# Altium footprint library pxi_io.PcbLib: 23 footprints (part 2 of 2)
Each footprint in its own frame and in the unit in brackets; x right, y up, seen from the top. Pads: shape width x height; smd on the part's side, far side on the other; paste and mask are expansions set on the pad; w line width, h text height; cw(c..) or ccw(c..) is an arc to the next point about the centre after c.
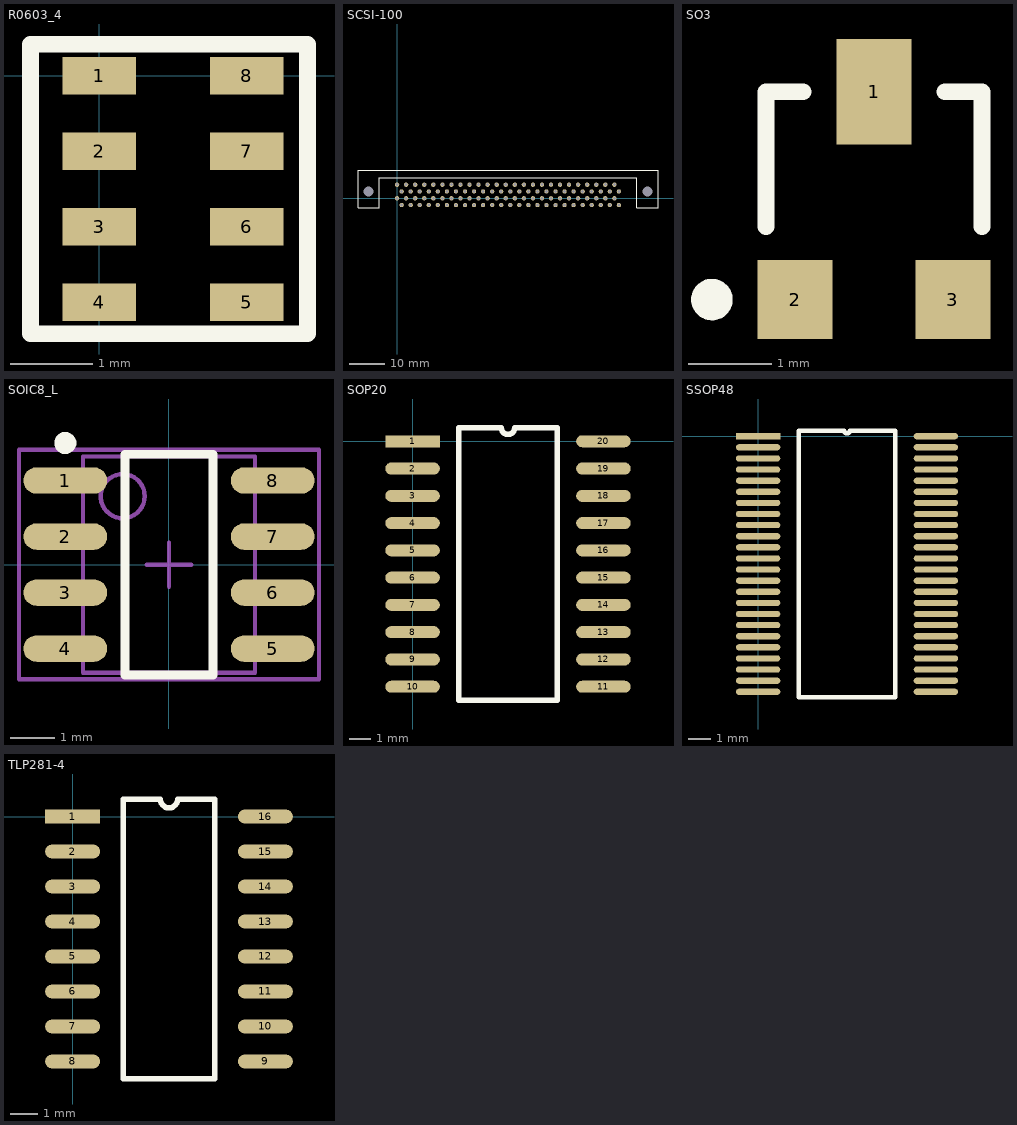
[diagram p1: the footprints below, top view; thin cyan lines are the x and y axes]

## R0603_4 [mil] "for ResPackX4____OK!"
pads (8):
  rect 35x18 smd: 1(0,0) 2(0,-36) 3(0,-72) 4(0,-108) 5(70.16,-108) 6(70.16,-72) 7(70.16,-36) 8(70.16,0)
Top Overlay:
  lines w8: -32.84,15 -32.84,-123 99.16,-123 99.16,15 -31.84,15

## SCSI-100 [mm]
pads (102):
  round 1.2 hole 0.85: 1(0,0) 2(1.27,-1.905) 3(2.54,0) 4(3.81,-1.905) 5(5.08,0) 6(6.35,-1.905) 7(7.62,0) 8(8.89,-1.905) 9(10.16,0) 10(11.43,-1.905) 11(12.7,0) 12(13.97,-1.905) 13(15.24,0) 14(16.51,-1.905) 15(17.78,0) 16(19.05,-1.905) 17(20.32,0) 18(21.59,-1.905) 19(22.86,0) 20(24.13,-1.905) 21(25.4,0) 22(26.67,-1.905) 23(27.94,0) 24(29.21,-1.905) 25(30.48,0) 26(31.75,-1.905) 27(33.02,0) 28(34.29,-1.905) 29(35.56,0) 30(36.83,-1.905) 31(38.1,0) 32(39.37,-1.905) 33(40.64,0) 34(41.91,-1.905) 35(43.18,0) 36(44.45,-1.905) 37(45.72,0) 38(46.99,-1.905) 39(48.26,0) 40(49.53,-1.905) 41(50.8,0) 42(52.07,-1.905) 43(53.34,0) 44(54.61,-1.905) 45(55.88,0) 46(57.15,-1.905) 47(58.42,0) 48(59.69,-1.905) 49(60.96,0) 50(62.23,-1.905) 51(0,3.81) 52(1.27,1.905) 53(2.54,3.81) 54(3.81,1.905) 55(5.08,3.81) 56(6.35,1.905) 57(7.62,3.81) 58(8.89,1.905) 59(10.16,3.81) 60(11.43,1.905) 61(12.7,3.81) 62(13.97,1.905) 63(15.24,3.81) 64(16.51,1.905) 65(17.78,3.81) 66(19.05,1.905) 67(20.32,3.81) 68(21.59,1.905) 69(22.86,3.81) 70(24.13,1.905) 71(25.4,3.81) 72(26.67,1.905) 73(27.94,3.81) 74(29.21,1.905) 75(30.48,3.81) 76(31.75,1.905) 77(33.02,3.81) 78(34.29,1.905) 79(35.56,3.81) 80(36.83,1.905) 81(38.1,3.81) 82(39.37,1.905) 83(40.64,3.81) 84(41.91,1.905) 85(43.18,3.81) 86(44.45,1.905) 87(45.72,3.81) 88(46.99,1.905) 89(48.26,3.81) 90(49.53,1.905) 91(50.8,3.81) 92(52.07,1.905) 93(53.34,3.81) 94(54.61,1.905) 95(55.88,3.81) 96(57.15,1.905) 97(58.42,3.81) 98(59.69,1.905) 99(60.96,3.81) 100(62.23,1.905)
  round 2.5 hole 2.77: 101(-8.01,1.905) 102(70.24,1.905)
Top Overlay:
  lines w0.254: -10.975,-2.667 -10.975,7.858 73.205,7.874 73.205,-2.667 67.265,-2.667 67.265,5.7 -5.035,5.715 -5.035,-2.667 -10.975,-2.667

## SO3 [mm]
pads (3):
  rect 0.9x1.27 smd: 1(2.972,-3.601)
  rect 0.9x0.95 smd: 2(2.022,-6.101) 3(3.922,-6.101)
Top Overlay:
  circle w0.25: c1.022,-6.101 r0.125
  lines w0.2: 1.672,-5.226 1.672,-3.601 2.122,-3.601 ; 3.822,-3.601 4.272,-3.601 4.272,-5.226

## SOIC8_L [mm] "SOIC, 8-Leads, Body 4.9x3.9mm, Pitch 1.27mm, IPC High Density"
height 1.75
pads (8):
  oval 1.9x0.6 smd: 1(-2.35,1.905) 2(-2.35,0.635) 3(-2.35,-0.635) 4(-2.35,-1.905) 5(2.35,-1.905) 6(2.35,-0.635) 7(2.35,0.635) 8(2.35,1.905)
Top Overlay:
  circle w0.25: c-2.35,2.755 r0.125
  lines w0.2: -1,-2.5 1,-2.5 1,2.5 -1,2.5 -1,-2.5
Mechanical 13:
  circle w0.1: c-1.05,1.55 r0.5
  lines w0.1: -1.95,-2.45 1.95,-2.45 1.95,2.45 -1.95,2.45 -1.95,-2.45
Mechanical 15:
  lines w0.1: -0.5,0 0.5,0 ; 0,-0.5 0,0.5 ; -3.4,-2.6 3.4,-2.6 3.4,2.6 -3.4,2.6 -3.4,-2.6
3D body: height 1.75, standoff 0, extent -1.95,-2.45 1.95,2.45

## SOP20 [mil]
pads (20):
  rect 100x22 smd: 1(0,0)
  oval 100x22 smd: 2(0,-50) 3(0,-100) 4(0,-150) 5(0,-200) 6(0,-250) 7(0,-300) 8(0,-350) 9(0,-400) 10(0,-450) 11(350,-450) 12(350,-400) 13(350,-350) 14(350,-300) 15(350,-250) 16(350,-200) 17(350,-150) 18(350,-100) 19(350,-50) 20(350,0)
Top Overlay:
  lines w10: 85,-475 85,25 162.5,25 ccw(c175,25) 187.5,25 265,25 265,-475 85,-475

## SSOP48 [mm]
pads (48):
  rect 2x0.28 smd: 1(0,0)
  oval 2x0.28 smd: 2(0,-0.5) 3(0,-1) 4(0,-1.5) 5(0,-2) 6(0,-2.5) 7(0,-3) 8(0,-3.5) 9(0,-4) 10(0,-4.5) 11(0,-5) 12(0,-5.5) 13(0,-6) 14(0,-6.5) 15(0,-7) 16(0,-7.5) 17(0,-8) 18(0,-8.5) 19(0,-9) 20(0,-9.5) 21(0,-10) 22(0,-10.5) 23(0,-11) 24(0,-11.5) 25(8,-11.5) 26(8,-11) 27(8,-10.5) 28(8,-10) 29(8,-9.5) 30(8,-9) 31(8,-8.5) 32(8,-8) 33(8,-7.5) 34(8,-7) 35(8,-6.5) 36(8,-6) 37(8,-5.5) 38(8,-5) 39(8,-4.5) 40(8,-4) 41(8,-3.5) 42(8,-3) 43(8,-2.5) 44(8,-2) 45(8,-1.5) 46(8,-1) 47(8,-0.5) 48(8,0)
Top Overlay:
  lines w0.2: 1.835,-11.75 1.835,0.25 3.875,0.25 ccw(c4,0.25) 4.125,0.25 6.165,0.25 6.165,-11.75 1.835,-11.75

## TLP281-4 [mm]
pads (16):
  rect 2x0.5 smd: 1(0,0)
  oval 2x0.5 smd: 2(0,-1.27) 3(0,-2.54) 4(0,-3.81) 5(0,-5.08) 6(0,-6.35) 7(0,-7.62) 8(0,-8.89) 9(7,-8.89) 10(7,-7.62) 11(7,-6.35) 12(7,-5.08) 13(7,-3.81) 14(7,-2.54) 15(7,-1.27) 16(7,0)
Top Overlay:
  lines w0.2: 1.835,-9.525 1.835,0.635 3.183,0.635 ccw(c3.5,0.635) 3.818,0.635 5.165,0.635 5.165,-9.525 1.835,-9.525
